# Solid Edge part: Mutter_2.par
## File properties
Sűrűség: 0,000 kg/m^3
Pontosság: 0,990
Author: ahadarics
Last saved by: ahadarics
Revision: 76
Username: ahadarics
Dokumentum tartalom típus: 0
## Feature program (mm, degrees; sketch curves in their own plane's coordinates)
base feature "unnamed BaseFeature 1"
thread "unnamed Thread 1"
chamfer "unnamed Chamfer 1"
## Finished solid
Body 1: solid body, 23 faces, 46 edges, 24 vertices.
  Faces by surface: cone 14, plane 8, cylinder 1
  Edges by curve: spline 24, circle 16, line 6
Bounding box of the edges (mm): 4.000 x 8.083 x 7.000, from (0, -4.0415, -3.5) to (4, 4.0415, 3.5).
Cylindrical faces by radius (mm): R1.621 x1
Conical faces (half-angle, radius in mm at the cone's reference point): 45 deg R1.621 x1, 45 deg R1.821 x1, 60 deg R3.7707 x12
Planar faces by outward normal: +x 1, +z 1, -x 1, -z 1, oblique 4
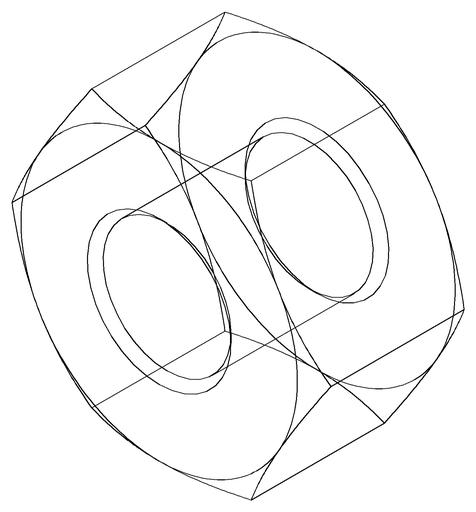
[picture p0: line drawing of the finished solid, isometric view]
